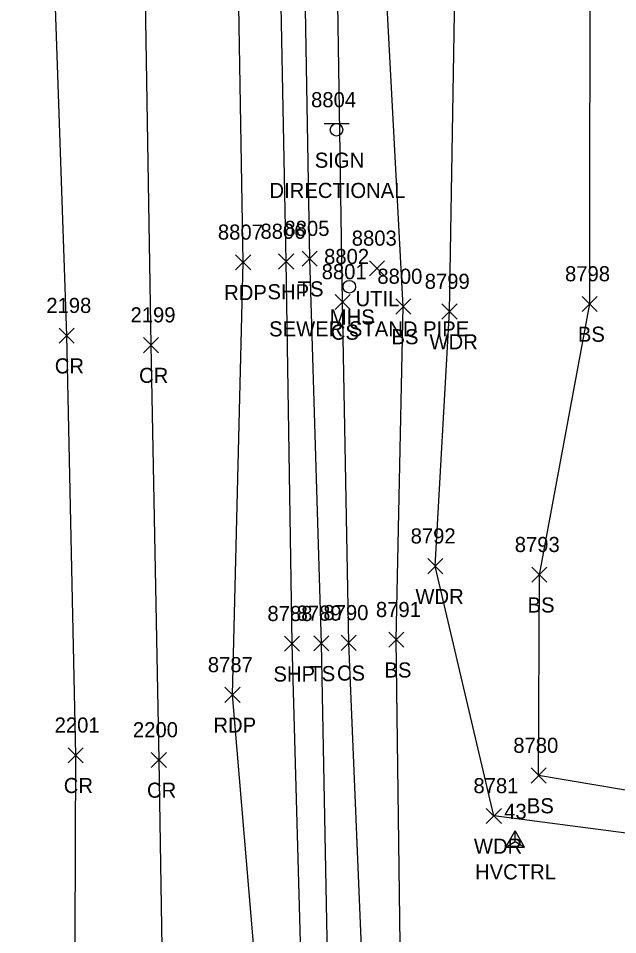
# Model space of a CAD drawing. Extents: x 1462089 to 1464015, y 730534 to 736144.
# Drawn here: x 1463227.5 to 1463306.8, y 734520.2 to 734641.4 of the extents above; entities that cross this region are included whole.
import ezdxf

# ---------------------------------------------------------------- set-up
doc = ezdxf.new("R2010")
doc.units = 0
for name, color, linetype in [('C_A', 7, 'Continuous'), ('C_I', 7, 'Continuous'), ('CPSM', 7, 'Continuous'), ('L_A', 7, 'Continuous'), ('L_I', 7, 'Continuous'), ('L_TIC', 7, 'Continuous'), ('LAWA', 7, 'Continuous'), ('LELB', 7, 'Continuous'), ('P_A', 7, 'Continuous'), ('P_I', 7, 'Continuous'), ('P_TIC', 7, 'Continuous'), ('PET', 7, 'Continuous'), ('PRC', 7, 'Continuous'), ('PSP', 7, 'Continuous'), ('S_A', 7, 'Continuous'), ('S_C', 7, 'Continuous'), ('S_I', 7, 'Continuous'), ('SSGN', 7, 'Continuous'), ('U_A', 7, 'Continuous'), ('U_C', 7, 'Continuous'), ('U_I', 7, 'Continuous'), ('UDEFAULT', 7, 'Continuous'), ('USMH', 7, 'Continuous')]:
    doc.layers.add(name, color=color, linetype=linetype)

msp = doc.modelspace()

# ---------------------------------------------------------------- linework, layer by layer
at = {"layer": 'CPSM'}
for p, q in [((1463291.96, 734531.81), (1463293.21, 734533.97)), ((1463294.46, 734531.81), (1463293.21, 734533.97)), ((1463293.21, 734532.53), (1463293.21, 734533.97)), ((1463291.96, 734531.81), (1463293.21, 734532.53)), ((1463291.96, 734531.81), (1463294.46, 734531.81)), ((1463293.21, 734532.53), (1463293.21, 734532.53)), ((1463293.21, 734532.53), (1463294.46, 734531.81))]:
    msp.add_line(p, q, dxfattribs=at)
at = {"layer": 'L_TIC'}
for points in [[(1463265.05, 734608.64), (1463267.05, 734610.64)], [(1463267.05, 734608.64), (1463265.05, 734610.64)], [(1463269.4, 734602.91), (1463271.4, 734604.91)], [(1463271.4, 734602.91), (1463269.4, 734604.91)], [(1463277.42, 734602.31), (1463279.42, 734604.31)], [(1463279.42, 734602.31), (1463277.42, 734604.31)], [(1463302.06, 734602.64), (1463304.06, 734604.64)], [(1463304.06, 734602.64), (1463302.06, 734604.64)], [(1463283.52, 734601.64), (1463285.52, 734603.64)], [(1463285.52, 734601.64), (1463283.52, 734603.64)], [(1463281.65, 734567.96), (1463283.65, 734569.96)], [(1463283.65, 734567.96), (1463281.65, 734569.96)], [(1463295.41, 734566.83), (1463297.41, 734568.83)], [(1463297.41, 734566.83), (1463295.41, 734568.83)], [(1463266.59, 734557.75), (1463268.59, 734559.75)], [(1463268.59, 734557.75), (1463266.59, 734559.75)], [(1463270.21, 734557.82), (1463272.21, 734559.82)], [(1463272.21, 734557.82), (1463270.21, 734559.82)], [(1463276.49, 734558.23), (1463278.49, 734560.23)], [(1463278.49, 734558.23), (1463276.49, 734560.23)], [(1463295.31, 734540.27), (1463297.31, 734542.27)], [(1463297.31, 734540.27), (1463295.31, 734542.27)], [(1463289.38, 734534.93), (1463291.38, 734536.93)], [(1463291.38, 734534.93), (1463289.38, 734536.93)]]:
    msp.add_lwpolyline(points, dxfattribs=at)
at = {"layer": 'LAWA'}
msp.add_lwpolyline([(1463325.36, 734531.35), (1463290.38, 734535.93), (1463282.65, 734568.96), (1463284.52, 734602.64), (1463285.26, 734647.37), (1463289, 734665.01), (1463295.84, 734662.53), (1463303.11, 734657.04), (1463320.15, 734643.47), (1463316.73, 734633.96)], dxfattribs=at)
at = {"layer": 'LELB'}
for points in [[(1463257.99, 733966.71), (1463259.97, 734009.79), (1463260.85, 734065.09), (1463262.42, 734118.18), (1463263.13, 734164.3), (1463264.61, 734217.86), (1463266.34, 734269.39), (1463268.59, 734322.49), (1463270.46, 734374.56), (1463270.28, 734418.89), (1463269.92, 734448.47), (1463273.46, 734458.19), (1463268.74, 734470.19), (1463268.59, 734508.22), (1463267.59, 734558.75), (1463266.05, 734609.64), (1463265.18, 734660.46), (1463264.37, 734673.7), (1463264.44, 734721.41), (1463263.51, 734771.24)], [(1463265.19, 733966.28), (1463265.78, 734009.31), (1463269.75, 734065.14), (1463271.38, 734117.71), (1463273.22, 734165), (1463277.32, 734216.35), (1463277.15, 734269.17), (1463280.6, 734320.8), (1463280.59, 734374.28), (1463280.93, 734418.68), (1463275.17, 734448.18), (1463281.28, 734462.13), (1463275.95, 734474.69), (1463273.3, 734509), (1463271.21, 734558.82), (1463270.4, 734603.91), (1463269.5, 734660.22), (1463269.15, 734674.46), (1463268.7, 734688.89), (1463268.89, 734721.54), (1463269.27, 734771.05)], [(1463275.52, 734034.35), (1463282.75, 734064.48), (1463283.26, 734113.05), (1463287.02, 734165), (1463290.21, 734212.93), (1463288.11, 734269.86), (1463292.5, 734320.4), (1463292.02, 734374.5), (1463289.96, 734418.33), (1463289.99, 734453.57), (1463287.89, 734482.05), (1463283.15, 734489.94), (1463278.14, 734508.89), (1463277.49, 734559.23), (1463278.42, 734603.31), (1463275.85, 734651.26), (1463277.33, 734664.39), (1463273.56, 734674.46), (1463272.19, 734688.18), (1463274.44, 734722.02), (1463275.24, 734770.64)], [(1463327.13, 734536.08), (1463296.31, 734541.27), (1463296.41, 734567.83), (1463303.06, 734603.64), (1463303.11, 734657.04), (1463303.32, 734701.07)]]:
    msp.add_lwpolyline(points, dxfattribs=at)
at = {"layer": 'P_TIC'}
for points in [[(1463256.25, 734608.15), (1463258.25, 734610.15)], [(1463258.25, 734608.15), (1463256.25, 734610.15)], [(1463261.93, 734608.26), (1463263.93, 734610.26)], [(1463263.93, 734608.26), (1463261.93, 734610.26)], [(1463232.92, 734598.45), (1463234.92, 734600.45)], [(1463234.92, 734598.45), (1463232.92, 734600.45)], [(1463244.06, 734597.2), (1463246.06, 734599.2)], [(1463246.06, 734597.2), (1463244.06, 734599.2)], [(1463262.72, 734557.7), (1463264.72, 734559.7)], [(1463264.72, 734557.7), (1463262.72, 734559.7)], [(1463254.84, 734550.94), (1463256.84, 734552.94)], [(1463256.84, 734550.94), (1463254.84, 734552.94)], [(1463234.11, 734542.95), (1463236.11, 734544.95)], [(1463236.11, 734542.95), (1463234.11, 734544.95)], [(1463245.1, 734542.33), (1463247.1, 734544.33)], [(1463247.1, 734542.33), (1463245.1, 734544.33)]]:
    msp.add_lwpolyline(points, dxfattribs=at)
at = {"layer": 'PET'}
msp.add_lwpolyline([(1463248.8, 733967.1), (1463249.86, 734010.39), (1463251.61, 734064.59), (1463253.36, 734118.27), (1463254.42, 734163.74), (1463255.79, 734217.97), (1463257.3, 734268.95), (1463258.94, 734322.75), (1463260.51, 734374.85), (1463260.98, 734418.78), (1463260.22, 734470.89), (1463259.54, 734508.02), (1463255.84, 734551.94), (1463257.25, 734609.15), (1463256.38, 734661.33), (1463256.42, 734674.99), (1463255.03, 734720.12), (1463254.12, 734771.84)], dxfattribs=at)
at = {"layer": 'PRC'}
for points in [[(1463228.58, 734798.08), (1463230.75, 734747.1), (1463230.44, 734700.4), (1463232, 734654.41), (1463233.92, 734599.45), (1463235.11, 734543.95), (1463234.91, 734495.86), (1463235.12, 734449.27), (1463236.23, 734398.03), (1463234.69, 734355.77), (1463233.49, 734307.13), (1463228.69, 734271.55), (1463231.41, 734217.81), (1463230.21, 734171), (1463228.59, 734116.25), (1463226.96, 734072.96), (1463226.23, 734016.91), (1463224.48, 733963.11)], [(1463241.52, 734797.52), (1463242.3, 734746.35), (1463243.09, 734699.96), (1463244.11, 734654.62), (1463245.06, 734598.2), (1463246.1, 734543.33), (1463246.89, 734493.71), (1463246.91, 734449.97), (1463246.92, 734397.87), (1463248.67, 734354.6), (1463245.97, 734304.67), (1463245.84, 734264.62), (1463244.04, 734215.96), (1463241.66, 734164.25), (1463240.71, 734114.74), (1463238.65, 734070.53), (1463237.77, 734016.4), (1463235.71, 733961.6)]]:
    msp.add_lwpolyline(points, dxfattribs=at)
at = {"layer": 'PSP'}
msp.add_lwpolyline([(1463255.54, 733966.95), (1463256.55, 734009.92), (1463257.79, 734064.75), (1463259.66, 734118.57), (1463259.79, 734164.74), (1463261.4, 734217.95), (1463262.55, 734269.57), (1463264.46, 734323.21), (1463266.28, 734374.26), (1463266.36, 734418.39), (1463265.4, 734469.43), (1463265.15, 734508.14), (1463263.72, 734558.7), (1463262.93, 734609.26), (1463261.91, 734661.14), (1463261.74, 734674.67), (1463260.61, 734721.09), (1463259.81, 734771.37)], dxfattribs=at)
at = {"layer": 'SSGN'}
for p, q in [((1463267.94, 734627.52), (1463271.27, 734627.52)), ((1463269.59, 734626.68), (1463269.59, 734626.68))]:
    msp.add_line(p, q, dxfattribs=at)
msp.add_circle((1463269.59, 734626.68), 0.833, dxfattribs=at)
at = {"layer": 'UDEFAULT'}
for points in [[(1463273.95, 734607.35), (1463275.95, 734609.35)], [(1463275.95, 734607.35), (1463273.95, 734609.35)]]:
    msp.add_lwpolyline(points, dxfattribs=at)
at = {"layer": 'USMH'}
for p, q in [((1463271.29, 734605.92), (1463271.29, 734605.92)), ((1463272.12, 734605.92), (1463272.12, 734605.92))]:
    msp.add_line(p, q, dxfattribs=at)
msp.add_circle((1463271.29, 734605.92), 0.833, dxfattribs=at)

# ---------------------------------------------------------------- texts
at = {"layer": 'C_A'}
msp.add_text('HVCTRL', height=2, dxfattribs=at).set_placement((1463287.9, 734527.53))
at = {"layer": 'C_I'}
msp.add_text('43', height=2, dxfattribs=at).set_placement((1463291.75, 734535.53))
at = {"layer": 'L_A'}
for s, p in [('TS', (1463264.46, 734604.64)), ('CS', (1463268.84, 734598.91)), ('BS', (1463301.5, 734598.64)), ('BS', (1463276.86, 734598.31)), ('WDR', (1463281.88, 734597.64)), ('WDR', (1463280.02, 734563.96)), ('BS', (1463294.85, 734562.83)), ('TS', (1463266, 734553.75)), ('CS', (1463269.65, 734553.82)), ('BS', (1463275.93, 734554.23)), ('BS', (1463294.75, 734536.27)), ('WDR', (1463287.75, 734530.93))]:
    msp.add_text(s, height=2, dxfattribs=at).set_placement(p)
at = {"layer": 'L_I'}
for s, p in [('8805', (1463262.71, 734612.64)), ('8801', (1463267.63, 734606.91)), ('8800', (1463274.99, 734606.31)), ('8798', (1463299.8, 734606.64)), ('8799', (1463281.25, 734605.64)), ('8792', (1463279.39, 734571.96)), ('8793', (1463293.15, 734570.83)), ('8791', (1463274.8, 734562.23)), ('8789', (1463264.32, 734561.75)), ('8790', (1463267.86, 734561.82)), ('8780', (1463292.96, 734544.27)), ('8781', (1463287.69, 734538.93))]:
    msp.add_text(s, height=2, dxfattribs=at).set_placement(p)
at = {"layer": 'P_A'}
for s, p in [('RDP', (1463254.74, 734604.15)), ('SHP', (1463260.47, 734604.26)), ('CR', (1463232.35, 734594.45)), ('CR', (1463243.49, 734593.2)), ('SHP', (1463261.25, 734553.7)), ('RDP', (1463253.32, 734546.94)), ('CR', (1463233.54, 734538.95)), ('CR', (1463244.54, 734538.33))]:
    msp.add_text(s, height=2, dxfattribs=at).set_placement(p)
at = {"layer": 'P_I'}
for s, p in [('8807', (1463253.91, 734612.15)), ('8806', (1463259.54, 734612.26)), ('2198', (1463231.23, 734602.45)), ('2199', (1463242.36, 734601.2)), ('8788', (1463260.46, 734561.7)), ('8787', (1463252.58, 734554.94)), ('2201', (1463232.33, 734546.95)), ('2200', (1463242.68, 734546.33))]:
    msp.add_text(s, height=2, dxfattribs=at).set_placement(p)
at = {"layer": 'S_A'}
msp.add_text('SIGN', height=2, dxfattribs=at).set_placement((1463266.72, 734621.66))
at = {"layer": 'S_C'}
msp.add_text('DIRECTIONAL', height=2, dxfattribs=at).set_placement((1463260.73, 734617.66))
at = {"layer": 'S_I'}
msp.add_text('8804', height=2, dxfattribs=at).set_placement((1463266.23, 734629.66))
at = {"layer": 'U_A'}
for s, p in [('UTIL', (1463272.11, 734603.35)), ('MHS', (1463268.7, 734600.92))]:
    msp.add_text(s, height=2, dxfattribs=at).set_placement(p)
at = {"layer": 'U_C'}
msp.add_text('SEWER STAND PIPE', height=2, dxfattribs=at).set_placement((1463260.68, 734599.35))
at = {"layer": 'U_I'}
for s, p in [('8803', (1463271.61, 734611.35)), ('8802', (1463267.95, 734608.92))]:
    msp.add_text(s, height=2, dxfattribs=at).set_placement(p)

doc.saveas('drawing.dxf')
